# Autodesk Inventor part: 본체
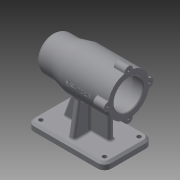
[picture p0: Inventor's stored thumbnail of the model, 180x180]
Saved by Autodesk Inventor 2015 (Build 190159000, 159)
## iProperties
Created: 2019-07
Part Number: 본체
Material: 일반
Document SubType Name: Modeling
Designer: now
Density: 1 g/cm^3
Appearance: 기본값
Author: now
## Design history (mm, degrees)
sketch "스케치1"
  geometry: L1 (-56, 35)-(56, 35); L2 (56, 35)-(56, -35); L3 (56, -35)-(-56, -35); L4 (-56, -35)-(-56, 35); L5 (-56, 35)-(56, -35); L6 (56, 35)-(-56, -35); 1 further point
  constraints: 12 end point, 2 midpoint, 2 parallel, 1 horizontal, 1 perpendicular
  dimensions: "d0" = 70 distance of L1.end L2.end; "d1" = 112 distance of L2.end L3.end
extrude "돌출1" new body sketch "스케치1" distance "d2" = 10; taper "d3" = 0 deg
sketch "스케치2"
  geometry: L1 (-46, 25)-(46, 25); L2 (46, 25)-(46, -25); L3 (46, -25)-(-46, -25); L4 (-46, -25)-(-46, 25); L5 (-46, 25)-(46, -25); L6 (46, 25)-(-46, -25); 1 further point
  constraints: 12 end point, 2 midpoint, 2 parallel, 1 horizontal, 1 perpendicular
  dimensions: "d4" = 92 distance of L2.end L3.end; "d5" = 50 distance of L1.end L2.end
hole "구멍1" sketch "스케치2" at (-46, -25), (46, -25), (46, 25), (-46, 25) diameter "d6" = 6; stored, may be unused: countersink angle "d10" = 90 deg, drill point angle "d12" = 118 deg; dims "d7" = 6, "d8" = 4, "d9" = 2, "d11" = 8
fillet "모깎기1" dims "d13" = 10
sketch "스케치3"
  geometry: L1 (-56, 25)-(-56, -25) reference; L2 (-46, -35)-(46, -35) reference; L3 (56, -25)-(56, 25) reference; L4 (-4, -28)-(4, -28); L5 (4, -28)-(4, 28); L6 (4, 28)-(-4, 28); L7 (-4, 28)-(-4, -28); L8 (-4, -28)-(4, 28); L9 (4, -28)-(-4, 28); L10 (-31, 4)-(31, -4); L11 (-36, 4)-(31, 4); L12 (31, 4)-(31, -4); L13 (31, -4)-(-36, -4); L14 (-36, -4)-(-36, 4); L15 (-36, 4)-(31, -4); L16 (31, 4)-(-36, -4); 2 further points
  constraints: 26 end point, 5 midpoint, 4 parallel, 2 horizontal, 2 perpendicular, 1 horizontal alignment
  dimensions: "d14" = 8 distance of L5.end L6.end; "d16" = 7 distance between parallel lines of L4 L2; "d18" = 25 distance between parallel lines of L3 L12; "d19" = 20 distance between parallel lines of L14 L1; "d20" = 8 distance of L11.end L12.end
extrude "돌출2" join sketch "스케치3" distance "d21" = 70; taper "d22" = 0 deg
node "작업 평면3"
sketch "스케치6"
  geometry: L1 (0, 0)-(0, 80); C1 r 30 at (0, 80)
  constraints: 2 end point, 1 centre point, 1 coincident, 1 vertical
  dimensions: "d29" = 80 distance of L1.start L1.end; "d30" = 60 diameter of C1
extrude "돌출4" join sketch "스케치6" distance "d31" = 67; taper "d32" = 0 deg
node "작업 평면5"
  node "작업 평면4"
sketch "스케치9"
  geometry: L1 (56, 10)-(56, 0) reference; L2 (56, 0)-(-56, 0) reference; L3 (-56, 0)-(-56, 10) reference; L4 (-56, 10)-(-31, 10) reference; L5 (-31, 10)-(-31, 50) reference; L6 (-31, 50)-(-56, 50) reference; L7 (-56, 50)-(-56, 110) reference; L8 (-56, 110)-(11, 110) reference; L9 (11, 110)-(11, 80) reference; L10 (11, 80)-(36, 80) reference; L11 (36, 80)-(36, 10) reference; L12 (36, 10)-(56, 10) reference; L13 (11, 80)-(31, 80); L14 (31, 80)-(31, 105); L15 (31, 105)-(11, 110); 1 further point
  constraints: 6 end point, 1 horizontal, 1 perpendicular
  dimensions: "d37" = 25 distance of L13.end L14.end; "d38" = 20 distance between parallel lines of L9 L14
revolve "회전1" sketch "스케치9" stored, may be unused: angle "d39" = 90 deg
sketch "스케치10"
  geometry: C1 r 25 at (0, 0); A1 r 25 centre (0, 0) between (-24.678, -4) and (-24.678, 4) reference; 1 further point
  constraints: 1 centre point, 1 coincident
  dimensions: "d40" = 50 diameter of C1
extrude "돌출5" join sketch "스케치10" distance "d41" = 25; taper "d42" = 0 deg
feature "면 기울기1" dims angle "d43" = 10 deg
hole "구멍2" diameter "d46" = 42; stored, may be unused: countersink angle "d50" = 90 deg, drill point angle "d52" = 0 deg; dims "d47" = 6, "d48" = 4, "d49" = 2, "d51" = 15, "d64" = 10, "d65" = 10
hole "구멍3" diameter "d57" = 48; stored, may be unused: countersink angle "d61" = 90 deg, drill point angle "d63" = 0 deg; dims "d55" = 10, "d56" = 10, "d58" = 6, "d59" = 4, "d60" = 2, "d62" = 54
hole "구멍4" diameter "d68" = 42; stored, may be unused: countersink angle "d72" = 90 deg, drill point angle "d74" = 0 deg; dims "d66" = 10, "d67" = 10, "d69" = 6, "d70" = 4, "d71" = 2, "d73" = 12
hole "구멍5" diameter "d77" = 35; stored, may be unused: countersink angle "d81" = 90 deg, drill point angle "d83" = 0 deg; dims "d75" = 10, "d76" = 10, "d78" = 6, "d79" = 4, "d80" = 2, "d82" = 18
hole "구멍6" diameter "d86" = 32; stored, may be unused: countersink angle "d90" = 90 deg, drill point angle "d92" = 0 deg; dims "d84" = 10, "d85" = 10, "d87" = 6, "d88" = 4, "d89" = 2, "d91" = 4
hole "구멍7" diameter "d95" = 21; stored, may be unused: countersink angle "d99" = 90 deg, drill point angle "d101" = 0 deg; dims "d93" = 10, "d94" = 10, "d96" = 6, "d97" = 4, "d98" = 2, "d100" = 3
fillet "모깎기2" dims "d102" = 0.3
fillet "모깎기3" dims "d103" = 3
sketch "스케치11"
  geometry: C1 r 6 at (-30, 0); 2 further points
  constraints: 1 centre point, 1 horizontal alignment, 1 other
  dimensions: "d104" = 12 diameter of C1
extrude "돌출6" join sketch "스케치11" distance "d105" = 16; taper "d106" = 0 deg
sketch "스케치12"
  geometry: A1 r 6 centre (-110, 0) between (-109.4, 5.97) and (-109.4, -5.97) reference; A2 r 6 centre (-80, -30) between (-85.97, -29.4) and (-74.03, -29.4) reference; A3 r 6 centre (-50, 0) between (-50.6, -5.97) and (-50.6, 5.97) reference; A4 r 6 centre (-80, 30) between (-74.03, 29.4) and (-85.97, 29.4) reference; 1 further point
hole "구멍8" sketch "스케치12" at (-110, 0), (-80, -30), (-50, 0), (-80, 30) diameter "d110" = 3.242; stored, may be unused: countersink angle "d114" = 90 deg, drill point angle "d116" = 118 deg; dims "d111" = 8, "d112" = 4, "d113" = 2, "d115" = 11
fillet "모깎기4" dims "d117" = 1
fillet "모깎기5" dims "d118" = 10
fillet "모깎기6" dims "d119" = 1
chamfer "모따기1" distance "d120" = 3; stored, may be unused: second distance "d121" = 2, angle "d122" = 45 deg
chamfer "모따기2" distance "d126" = 1; stored, may be unused: second distance "d127" = 2, angle "d128" = 45 deg
node "작업 평면6"
sketch "스케치13"
  geometry: L1 (63.073, 80)-(-60.986, 80); L2 (46, 0)-(-46, 0) reference; L3 (56, 109.226)-(56, 86.771) reference; 2 further points
  constraints: 2 end point, 1 horizontal, 1 point on line, 1 other
  dimensions: "d130" = 80 distance between parallel lines of L1 L2; "d131" = 42 distance from line of point (14, 80) L3
feature "엠보싱1" sketch "스케치13" dims "d132" = 0.5, "d133" = 0
feature "면 기울기2" dims angle "d134" = 20 deg
fillet "모깎기10" dims "d135" = 3
fillet "모깎기11" dims "d136" = 3
fillet "모깎기12" dims "d137" = 3
node "솔리드1"
pattern_circular "원형 패턴1" dims angle "d108" = 360 deg
node "절단 모서리 투영1"
other parameters: "d28" = 56, "d33" = -67, "d129" = -30.5
